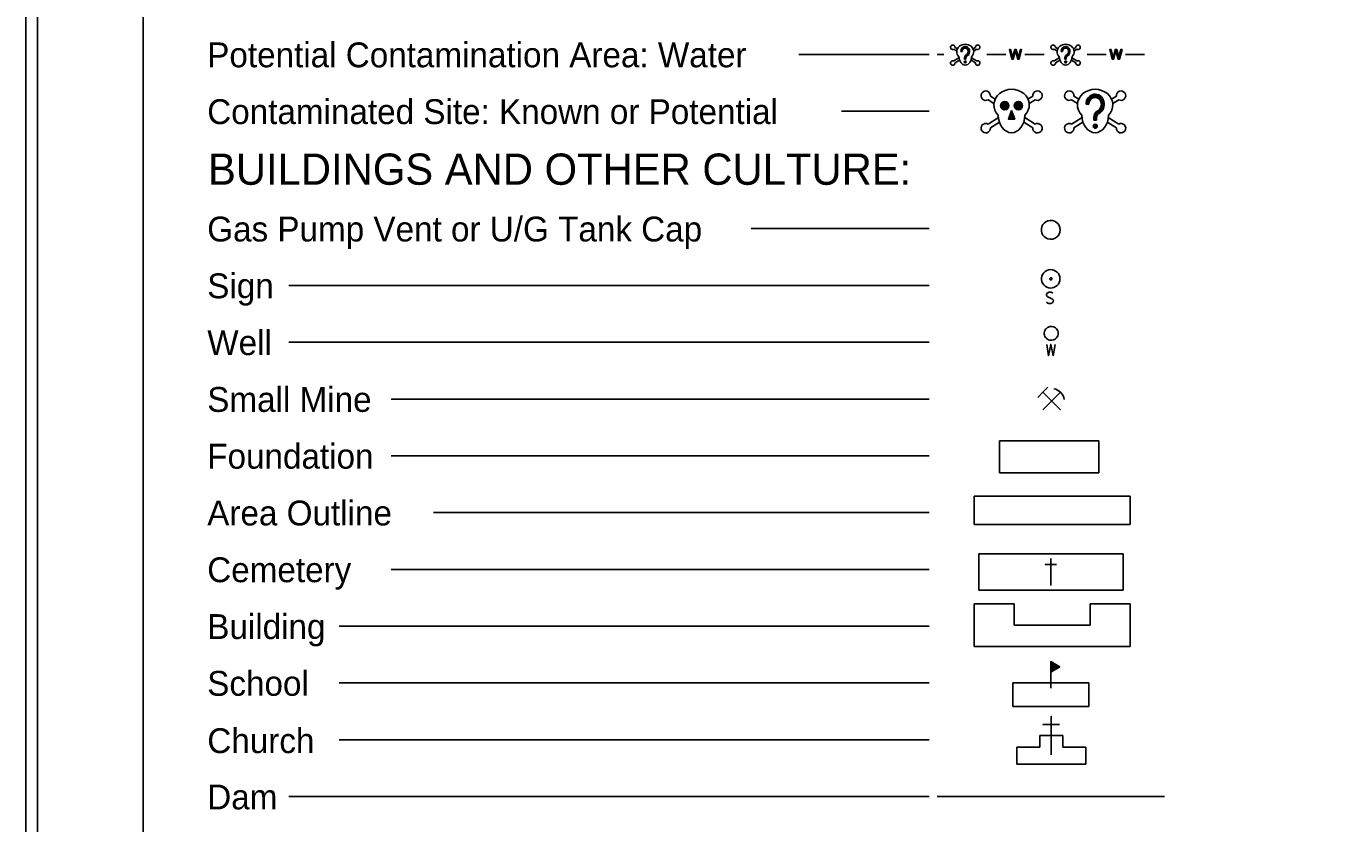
# Model space of a CAD drawing. Extents: x 811137 to 813186, y 647386 to 648494.
# Drawn here: x 811136.6 to 811598.2, y 647662.4 to 647945.6 of the extents above; entities that cross this region are included whole.
import ezdxf

# ---------------------------------------------------------------- set-up
doc = ezdxf.new("R2010")
doc.units = 0
for name, color, linetype in [('Default', 7, 'Continuous'), ('Sheet_Plan', 7, 'Continuous'), ('Sheet_Symbology', 7, 'Continuous'), ('z - Construction', 7, 'Continuous')]:
    doc.layers.add(name, color=color, linetype=linetype)

msp = doc.modelspace()

# ---------------------------------------------------------------- linework, layer by layer
at = {"layer": 'Default'}
msp.add_lwpolyline([(812820.63, 648494.02), (811136.63, 648494.02), (811136.63, 647394.02), (812820.63, 647394.02)], close=True, dxfattribs=at)
at = {"layer": 'Sheet_Plan'}
msp.add_line((811178.28, 647423.58), (811178.27, 648448.58), dxfattribs=at)
at = {"layer": 'Sheet_Symbology'}
for p, q in [((811466.71, 647937.98), (811467.53, 647937.46)), ((811473.95, 647937.98), (811473.13, 647937.46)), ((811502.37, 647937.98), (811503.2, 647937.46)), ((811509.62, 647937.98), (811508.79, 647937.46)), ((811457.46, 647935.49), (811411.27, 647935.49)), ((811460.36, 647935.5), (811462.69, 647935.5)), ((811466.31, 647937.34), (811467.32, 647936.7)), ((811468.08, 647934.29), (811466.31, 647933.17)), ((811468.25, 647933.5), (811466.71, 647932.53)), ((811468.77, 647936.56), (811469.25, 647936.56)), ((811470.09, 647934.28), (811470.09, 647933.86)), ((811470.09, 647933.86), (811470.57, 647933.86)), ((811470.16, 647934.28), (811470.16, 647933.86)), ((811470.23, 647934.28), (811470.23, 647933.86)), ((811470.3, 647934.28), (811470.3, 647933.86)), ((811470.33, 647935.5), (811470.33, 647935.5)), ((811470.36, 647934.28), (811470.36, 647933.86)), ((811470.43, 647934.28), (811470.43, 647933.86)), ((811470.5, 647934.28), (811470.5, 647933.86)), ((811470.57, 647934.28), (811470.57, 647933.86)), ((811472.41, 647933.5), (811473.95, 647932.53)), ((811472.58, 647934.29), (811474.35, 647933.17)), ((811474.35, 647937.34), (811473.34, 647936.7)), ((811477.97, 647935.5), (811484.77, 647935.5)), ((811491.56, 647935.5), (811498.35, 647935.5)), ((811501.97, 647937.34), (811502.99, 647936.7)), ((811503.75, 647934.29), (811501.97, 647933.17)), ((811503.92, 647933.5), (811502.37, 647932.53)), ((811504.44, 647936.56), (811504.92, 647936.56)), ((811505.76, 647934.28), (811505.76, 647933.86)), ((811505.76, 647933.86), (811506.24, 647933.86)), ((811505.82, 647934.28), (811505.82, 647933.86)), ((811505.89, 647934.28), (811505.89, 647933.86)), ((811505.96, 647934.28), (811505.96, 647933.86)), ((811506, 647935.5), (811506, 647935.5)), ((811506.03, 647934.28), (811506.03, 647933.86)), ((811506.1, 647934.28), (811506.1, 647933.86)), ((811506.17, 647934.28), (811506.17, 647933.86)), ((811506.24, 647934.28), (811506.24, 647933.86)), ((811508.07, 647933.5), (811509.62, 647932.53)), ((811508.24, 647934.29), (811510.02, 647933.17)), ((811510.02, 647937.34), (811509, 647936.7)), ((811513.64, 647935.5), (811520.43, 647935.5)), ((811527.23, 647935.5), (811534.02, 647935.5)), ((811478.43, 647919.38), (811480.55, 647918.05)), ((811479.27, 647920.71), (811480.98, 647919.64)), ((811494.33, 647920.71), (811492.62, 647919.64)), ((811495.17, 647919.38), (811493.05, 647918.05)), ((811508.12, 647919.38), (811510.24, 647918.05)), ((811508.96, 647920.71), (811510.67, 647919.64)), ((811524.02, 647920.71), (811522.31, 647919.64)), ((811524.86, 647919.38), (811522.74, 647918.05)), ((811457.46, 647915.31), (811426.34, 647915.31)), ((811486.8, 647915.05), (811486.8, 647915.05)), ((811513.25, 647917.76), (811514.25, 647917.76)), ((811516.49, 647915.57), (811516.49, 647915.57)), ((811482.13, 647913.04), (811478.43, 647910.72)), ((811482.48, 647911.41), (811479.27, 647909.39)), ((811491.12, 647911.41), (811494.33, 647909.39)), ((811491.47, 647913.04), (811495.17, 647910.72)), ((811511.82, 647913.04), (811508.12, 647910.72)), ((811512.17, 647911.41), (811508.96, 647909.39)), ((811515.99, 647913.03), (811515.99, 647912.15)), ((811515.99, 647912.15), (811516.99, 647912.15)), ((811516.13, 647913.03), (811516.13, 647912.15)), ((811516.28, 647913.03), (811516.28, 647912.15)), ((811516.42, 647913.03), (811516.42, 647912.15)), ((811516.56, 647913.03), (811516.56, 647912.15)), ((811516.71, 647913.03), (811516.71, 647912.15)), ((811516.85, 647913.03), (811516.85, 647912.15)), ((811516.99, 647913.03), (811516.99, 647912.15)), ((811520.81, 647911.41), (811524.02, 647909.39)), ((811521.16, 647913.04), (811524.86, 647910.72)), ((811457.46, 647873.6), (811394.31, 647873.6)), ((811457.46, 647853.42), (811230.02, 647853.42)), ((811457.46, 647833.24), (811230.02, 647833.24)), ((811457.46, 647813.06), (811266.34, 647813.06)), ((811497.93, 647815.44), (811496.11, 647813.62)), ((811497.93, 647809.16), (811504.21, 647815.44)), ((811501.07, 647812.3), (811500.71, 647812.65)), ((811501.07, 647812.3), (811504.21, 647809.16)), ((811482.47, 647798.16), (811517.78, 647798.16)), ((811482.47, 647786.88), (811482.47, 647798.16)), ((811517.78, 647798.16), (811517.78, 647786.88)), ((811457.46, 647792.88), (811266.34, 647792.88)), ((811517.78, 647786.88), (811482.47, 647786.88)), ((811528.95, 647778.55), (811473.46, 647778.55)), ((811473.46, 647778.55), (811473.46, 647768.46)), ((811528.95, 647768.46), (811528.95, 647778.55)), ((811457.46, 647772.7), (811281.42, 647772.7)), ((811473.46, 647768.46), (811528.95, 647768.46)), ((811475.13, 647758), (811526.44, 647758)), ((811475.13, 647745.08), (811475.13, 647758)), ((811526.44, 647758), (811526.44, 647745.08)), ((811457.46, 647752.52), (811266.34, 647752.52)), ((811526.44, 647745.08), (811475.13, 647745.08)), ((811487.75, 647740.25), (811473.46, 647740.25)), ((811473.46, 647740.25), (811473.46, 647725.12)), ((811487.75, 647732.68), (811487.75, 647740.25)), ((811528.95, 647740.25), (811514.66, 647740.25)), ((811514.66, 647740.25), (811514.66, 647732.68)), ((811528.95, 647725.12), (811528.95, 647740.25)), ((811457.46, 647732.34), (811247.89, 647732.34)), ((811514.66, 647732.68), (811487.75, 647732.68)), ((811473.46, 647725.12), (811528.95, 647725.12)), ((811457.46, 647712.17), (811247.89, 647712.17)), ((811487.26, 647712.17), (811514.22, 647712.17)), ((811487.26, 647703.79), (811487.26, 647712.17)), ((811514.22, 647712.17), (811514.22, 647703.79)), ((811514.22, 647703.79), (811487.26, 647703.79)), ((811504.96, 647693.49), (811496.79, 647693.49)), ((811496.79, 647693.49), (811496.79, 647689.41)), ((811504.96, 647689.41), (811504.96, 647693.49)), ((811457.46, 647691.99), (811247.89, 647691.99)), ((811496.79, 647689.41), (811488.62, 647689.41)), ((811488.62, 647689.41), (811488.62, 647683.27)), ((811513.14, 647689.41), (811504.96, 647689.41)), ((811513.14, 647683.27), (811513.14, 647689.41)), ((811488.62, 647683.27), (811513.14, 647683.27)), ((811457.46, 647671.81), (811230.02, 647671.81)), ((811460.36, 647671.81), (811541.07, 647671.81))]:
    msp.add_line(p, q, dxfattribs=at)
for points in [[(811488.09, 647936.39), (811487.37, 647933.8), (811486.91, 647933.8), (811486.01, 647937.2), (811486.47, 647937.2), (811486.99, 647934.97)], [(811487.28, 647934.9), (811487.93, 647937.2), (811488.47, 647937.2), (811488.96, 647935.48)], [(811489.39, 647935.02), (811489.92, 647937.2), (811490.38, 647937.2), (811489.45, 647933.8), (811489.01, 647933.8), (811488.3, 647936.39)], [(811523.75, 647936.39), (811523.04, 647933.8), (811522.58, 647933.8), (811521.67, 647937.2), (811522.13, 647937.2), (811522.65, 647934.97)], [(811522.95, 647934.9), (811523.6, 647937.2), (811524.14, 647937.2), (811524.62, 647935.48)], [(811525.06, 647935.02), (811525.59, 647937.2), (811526.04, 647937.2), (811525.11, 647933.8), (811524.68, 647933.8), (811523.96, 647936.39)], [(811504.1, 647873.17), (811503.92, 647873.97), (811503.74, 647874.69), (811503.3, 647875.31), (811502.67, 647875.85), (811502.04, 647876.21), (811501.33, 647876.48), (811500.52, 647876.48), (811499.72, 647876.38), (811499, 647876.03), (811498.38, 647875.58), (811497.93, 647875.04), (811497.57, 647874.33), (811497.39, 647873.52), (811497.39, 647872.81), (811497.57, 647872.01), (811497.93, 647871.29), (811498.38, 647870.75), (811499, 647870.31), (811499.72, 647869.95), (811500.52, 647869.86), (811501.33, 647869.86), (811502.04, 647870.13), (811502.67, 647870.49), (811503.3, 647871.02), (811503.74, 647871.65), (811503.92, 647872.36), (811504.1, 647873.17)], [(811504, 647855.76), (811503.94, 647856.41), (811503.74, 647857.07), (811503.41, 647857.66), (811502.96, 647858.12), (811502.43, 647858.51), (811501.84, 647858.84), (811501.25, 647858.97), (811500.53, 647859.04), (811499.88, 647858.91), (811499.29, 647858.71), (811498.7, 647858.38), (811498.24, 647857.92), (811497.84, 647857.33), (811497.58, 647856.74), (811497.45, 647856.09), (811497.45, 647855.43), (811497.58, 647854.78), (811497.84, 647854.19), (811498.24, 647853.6), (811498.7, 647853.14), (811499.29, 647852.81), (811499.88, 647852.61), (811500.53, 647852.48), (811501.25, 647852.55), (811501.84, 647852.68), (811502.43, 647853.01), (811502.96, 647853.4), (811503.41, 647853.86), (811503.74, 647854.45), (811503.94, 647855.1), (811504, 647855.76)], [(811500.86, 647856.15), (811500.66, 647856.15), (811500.46, 647856.02), (811500.33, 647855.83), (811500.4, 647855.63), (811500.53, 647855.43), (811500.73, 647855.37), (811500.92, 647855.43), (811501.05, 647855.56), (811501.12, 647855.83), (811501.05, 647856.02), (811500.86, 647856.15)], [(811501.5, 647850.71), (811500.86, 647851), (811500.13, 647851), (811499.46, 647850.71), (811499.18, 647850.2), (811499.18, 647850.01), (811499.49, 647849.53), (811501.34, 647848.58), (811501.65, 647848.14), (811501.62, 647847.75), (811501.34, 647847.25), (811500.8, 647846.96), (811500.03, 647846.96), (811499.68, 647847.09), (811499.18, 647847.44)], [(811503.4, 647836.37), (811503.32, 647836.81), (811503.24, 647837.25), (811503.04, 647837.64), (811502.76, 647838), (811502.45, 647838.32), (811502.09, 647838.56), (811501.65, 647838.72), (811501.21, 647838.84), (811500.78, 647838.84), (811500.34, 647838.8), (811499.9, 647838.64), (811499.55, 647838.44), (811499.19, 647838.16), (811498.87, 647837.84), (811498.67, 647837.45), (811498.51, 647837.05), (811498.43, 647836.61), (811498.43, 647836.14), (811498.51, 647835.7), (811498.67, 647835.3), (811498.87, 647834.91), (811499.19, 647834.59), (811499.55, 647834.31), (811499.9, 647834.11), (811500.34, 647833.95), (811500.78, 647833.91), (811501.21, 647833.91), (811501.65, 647834.03), (811502.09, 647834.19), (811502.45, 647834.43), (811502.76, 647834.75), (811503.04, 647835.1), (811503.24, 647835.5), (811503.32, 647835.94), (811503.4, 647836.37)], [(811499.28, 647832.48), (811499.91, 647828.45), (811500.74, 647832.48), (811501.56, 647828.45), (811502.26, 647832.48)], [(811501.07, 647812.3), (811497.93, 647815.44), (811499.7, 647817.21)], [(811505.48, 647812.86), (811505.32, 647813.57), (811505.07, 647814.22), (811504.72, 647814.83), (811504.26, 647815.34), (811503.75, 647815.84), (811503.15, 647816.2), (811502.49, 647816.5), (811501.83, 647816.66)], [(811500.8, 647746.82), (811500.8, 647756.28), (811500.8, 647754.27), (811498.79, 647754.27), (811502.81, 647754.27)], [(811500.78, 647710.29), (811500.78, 647719.74), (811503.94, 647717.88), (811500.78, 647716.02), (811500.96, 647716.32), (811500.96, 647719.48), (811503.57, 647717.85), (811501.15, 647716.43), (811501.19, 647719.19), (811503.27, 647717.85), (811501.37, 647716.77), (811501.37, 647718.85), (811502.94, 647717.85), (811501.6, 647717.1), (811501.6, 647718.52), (811502.6, 647717.88), (811501.78, 647717.4), (811501.78, 647718.18), (811502.3, 647717.88), (811501.97, 647717.7), (811501.93, 647717.92), (811502.04, 647717.88)], [(811500.88, 647686.68), (811500.88, 647700.3), (811500.88, 647697.4), (811497.98, 647697.4), (811503.77, 647697.4)]]:
    msp.add_lwpolyline(points, dxfattribs=at)
for points in [[(811486.8, 647915.57), (811485.69, 647912.54), (811487.91, 647912.54)], [(811486.8, 647915.05), (811485.95, 647912.72), (811487.65, 647912.72)], [(811486.8, 647914.54), (811486.2, 647912.9), (811487.4, 647912.9)], [(811486.8, 647914.02), (811486.45, 647913.07), (811487.15, 647913.07)], [(811486.8, 647913.51), (811486.7, 647913.25), (811486.9, 647913.25)]]:
    msp.add_lwpolyline(points, close=True, dxfattribs=at)
for centre, radius in [((811470.35, 647932.81), 0.344), ((811470.35, 647932.81), 0.267), ((811470.35, 647932.81), 0.19), ((811470.35, 647932.81), 0.113), ((811470.35, 647932.81), 0.0367), ((811506.01, 647932.81), 0.344), ((811506.01, 647932.81), 0.267), ((811506.01, 647932.81), 0.19), ((811506.01, 647932.81), 0.113), ((811506.01, 647932.81), 0.0367), ((811484.37, 647917.28), 1.5), ((811484.37, 647917.28), 1.32), ((811484.37, 647917.28), 1.14), ((811484.37, 647917.28), 0.968), ((811484.37, 647917.28), 0.791), ((811484.37, 647917.28), 0.614), ((811484.37, 647917.28), 0.438), ((811484.37, 647917.28), 0.261), ((811484.37, 647917.28), 0.0847), ((811489.23, 647917.28), 1.5), ((811489.23, 647917.28), 1.32), ((811489.23, 647917.28), 1.14), ((811489.23, 647917.28), 0.968), ((811489.23, 647917.28), 0.791), ((811489.23, 647917.28), 0.614), ((811489.23, 647917.28), 0.438), ((811489.23, 647917.28), 0.261), ((811489.23, 647917.28), 0.0847), ((811516.53, 647909.98), 0.715), ((811516.53, 647909.98), 0.556), ((811516.53, 647909.98), 0.394), ((811516.53, 647909.98), 0.235), ((811516.53, 647909.98), 0.0762)]:
    msp.add_circle(centre, radius, dxfattribs=at)
for centre, radius, start, end in [((811465.91, 647938.03), 0.805, 355.8976, 299.8062), ((811474.75, 647938.03), 0.805, 240.1938, 184.1024), ((811501.57, 647938.03), 0.805, 355.8976, 299.8062), ((811510.42, 647938.03), 0.805, 240.1938, 184.1024), ((811465.91, 647932.47), 0.805, 60.1938, 4.1024), ((811474.75, 647932.47), 0.805, 175.8976, 119.8062), ((811501.57, 647932.47), 0.805, 60.1938, 4.1024), ((811510.42, 647932.47), 0.805, 175.8976, 119.8062), ((811477.6, 647920.83), 1.67, 355.8976, 299.8062), ((811496, 647920.83), 1.67, 240.1938, 184.1024), ((811507.29, 647920.83), 1.67, 355.8976, 299.8062), ((811525.69, 647920.83), 1.67, 240.1938, 184.1024), ((811477.6, 647909.27), 1.67, 60.1938, 4.1024), ((811496, 647909.27), 1.67, 175.8976, 119.8062), ((811507.29, 647909.27), 1.67, 60.1938, 4.1024), ((811525.69, 647909.27), 1.67, 175.8976, 119.8062)]:
    msp.add_arc(centre, radius, start, end, dxfattribs=at)
for centre, major_axis, ratio, start_param, end_param in [((811470.33, 647936.45), (3.02, 0), 0.885014, 5.564242, 10.143721), ((811470.33, 647936.56), (0, 1.73), 0.9, 3.567618, 7.853982), ((811470.33, 647936.56), (0, 1.66), 0.9, 3.567618, 7.853982), ((811470.33, 647936.56), (0, 1.58), 0.9, 3.567618, 7.853982), ((811470.33, 647936.56), (0, 1.5), 0.9, 3.567618, 7.853982), ((811470.33, 647936.56), (0, 1.43), 0.9, 3.567618, 7.853982), ((811470.33, 647936.56), (0, 1.35), 0.9, 3.567618, 7.853982), ((811470.33, 647936.56), (0, 1.27), 0.9, 3.567618, 7.853982), ((811470.33, 647936.56), (0, 1.2), 0.9, 3.567618, 7.853982), ((811506, 647936.45), (3.02, 0), 0.885014, 5.564242, 10.143721), ((811506, 647936.56), (0, 1.73), 0.9, 3.567618, 7.853982), ((811506, 647936.56), (0, 1.66), 0.9, 3.567618, 7.853982), ((811506, 647936.56), (0, 1.58), 0.9, 3.567618, 7.853982), ((811506, 647936.56), (0, 1.5), 0.9, 3.567618, 7.853982), ((811506, 647936.56), (0, 1.43), 0.9, 3.567618, 7.853982), ((811506, 647936.56), (0, 1.35), 0.9, 3.567618, 7.853982), ((811506, 647936.56), (0, 1.27), 0.9, 3.567618, 7.853982), ((811506, 647936.56), (0, 1.2), 0.9, 3.567618, 7.853982), ((811470.33, 647934.73), (0, -3.02), 0.752542, 4.722735, 7.843636), ((811471.26, 647934.28), (0, 1.3), 0.9, 0.426026, 1.570796), ((811471.26, 647934.28), (0, 1.22), 0.9, 0.426026, 1.570796), ((811471.26, 647934.28), (0, 1.15), 0.9, 0.426026, 1.570796), ((811471.26, 647934.28), (0, 1.07), 0.9, 0.426026, 1.570796), ((811471.26, 647934.28), (0, 0.994), 0.9, 0.426026, 1.570796), ((811471.26, 647934.28), (0, 0.917), 0.9, 0.426026, 1.570796), ((811471.26, 647934.28), (0, 0.841), 0.9, 0.426026, 1.570796), ((811471.26, 647934.28), (0, 0.764), 0.9, 0.426026, 1.570796), ((811506, 647934.73), (0, -3.02), 0.752542, 4.722735, 7.843636), ((811506.92, 647934.28), (0, 1.3), 0.9, 0.426026, 1.570796), ((811506.92, 647934.28), (0, 1.22), 0.9, 0.426026, 1.570796), ((811506.92, 647934.28), (0, 1.15), 0.9, 0.426026, 1.570796), ((811506.92, 647934.28), (0, 1.07), 0.9, 0.426026, 1.570796), ((811506.92, 647934.28), (0, 0.994), 0.9, 0.426026, 1.570796), ((811506.92, 647934.28), (0, 0.917), 0.9, 0.426026, 1.570796), ((811506.92, 647934.28), (0, 0.841), 0.9, 0.426026, 1.570796), ((811506.92, 647934.28), (0, 0.764), 0.9, 0.426026, 1.570796), ((811486.8, 647917.55), (6.28, 0), 0.885014, 5.564242, 10.143721), ((811516.49, 647917.55), (6.28, 0), 0.885014, 5.564242, 10.143721), ((811516.49, 647917.76), (0, 3.6), 0.9, 3.567618, 7.853982), ((811516.49, 647917.76), (0, 3.44), 0.9, 3.567618, 7.853982), ((811516.49, 647917.76), (0, 3.28), 0.9, 3.567618, 7.853982), ((811516.49, 647917.76), (0, 3.13), 0.9, 3.567618, 7.853982), ((811516.49, 647917.76), (0, 2.97), 0.9, 3.567618, 7.853982), ((811516.49, 647917.76), (0, 2.81), 0.9, 3.567618, 7.853982), ((811516.49, 647917.76), (0, 2.65), 0.9, 3.567618, 7.853982), ((811516.49, 647917.76), (0, 2.49), 0.9, 3.567618, 7.853982), ((811518.42, 647913.03), (0, 2.7), 0.9, 0.426026, 1.570796), ((811518.42, 647913.03), (0, 2.54), 0.9, 0.426026, 1.570796), ((811518.42, 647913.03), (0, 2.38), 0.9, 0.426026, 1.570796), ((811518.42, 647913.03), (0, 2.22), 0.9, 0.426026, 1.570796), ((811518.42, 647913.03), (0, 2.07), 0.9, 0.426026, 1.570796), ((811518.42, 647913.03), (0, 1.91), 0.9, 0.426026, 1.570796), ((811518.42, 647913.03), (0, 1.75), 0.9, 0.426026, 1.570796), ((811518.42, 647913.03), (0, 1.59), 0.9, 0.426026, 1.570796), ((811486.8, 647913.96), (0, -6.28), 0.752542, 4.722735, 7.843636), ((811516.49, 647913.96), (0, -6.28), 0.752542, 4.722735, 7.843636)]:
    msp.add_ellipse(centre, major_axis=major_axis, ratio=ratio, start_param=start_param, end_param=end_param, dxfattribs=at)
for points in [[(811486.99, 647934.97), (811487.07, 647934.62), (811487.13, 647934.28)], [(811487.13, 647934.28), (811487.26, 647934.82), (811487.28, 647934.9)], [(811488.19, 647936.79), (811488.13, 647936.56), (811488.09, 647936.39)], [(811488.3, 647936.39), (811488.21, 647936.71), (811488.19, 647936.79)], [(811488.96, 647935.48), (811489.14, 647934.84), (811489.22, 647934.28)], [(811489.22, 647934.28), (811489.29, 647934.6), (811489.39, 647935.02)], [(811522.65, 647934.97), (811522.74, 647934.62), (811522.8, 647934.28)], [(811522.8, 647934.28), (811522.93, 647934.82), (811522.95, 647934.9)], [(811523.86, 647936.79), (811523.8, 647936.56), (811523.75, 647936.39)], [(811523.96, 647936.39), (811523.87, 647936.71), (811523.86, 647936.79)], [(811524.62, 647935.48), (811524.81, 647934.84), (811524.89, 647934.28)], [(811524.89, 647934.28), (811524.95, 647934.6), (811525.06, 647935.02)]]:
    msp.add_open_spline(points, degree=2, dxfattribs=at)
at = {"layer": 'z - Construction'}
msp.add_line((811140.78, 648486.08), (811140.78, 647386.08), dxfattribs=at)

# ---------------------------------------------------------------- texts
at = {"layer": 'Sheet_Symbology'}
for s, height, p in [('Potential Contamination Area: Water', 8.8282, (811201.02, 647930.92)), ('Contaminated Site: Known or Potential', 8.8282, (811201.02, 647910.74)), ('BUILDINGS AND OTHER CULTURE:', 11.0983, (811201.3, 647889.18)), ('Gas Pump Vent or U/G Tank Cap', 8.8282, (811201.02, 647869.03)), ('Sign', 8.828, (811201.03, 647848.86)), ('Well', 8.828, (811201.03, 647828.68)), ('Small Mine', 8.828, (811201.03, 647808.49)), ('Foundation', 8.828, (811201.03, 647788.31)), ('Area Outline', 8.8282, (811201.03, 647768.14)), ('Cemetery', 8.828, (811201.02, 647747.97)), ('Building', 8.828, (811201.03, 647727.79)), ('School', 8.828, (811201.02, 647707.61)), ('Church', 8.828, (811201.05, 647687.24)), ('Dam', 8.828, (811201.03, 647667.25))]:
    msp.add_text(s, height=height, dxfattribs=at).set_placement(p)

doc.saveas('drawing.dxf')
